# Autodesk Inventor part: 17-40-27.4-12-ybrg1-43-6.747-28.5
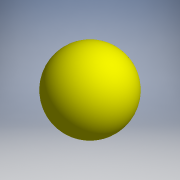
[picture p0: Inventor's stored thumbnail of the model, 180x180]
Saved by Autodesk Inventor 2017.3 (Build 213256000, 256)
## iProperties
Part Number: 17-40-27.4-12-ybrg1-43-6.747-28.5
Material: Generic
Catalog Web Link: www.cadenas.de
Description: Ball for Y units-Y-bearings
Vendor: SKF
Document SubType Name: Modeling
Designer: partserver
Manufacturer: SKF
Mass: 0.160817 g
Surface Area: 1.43012 cm^2
Volume: 0.160817 cm^3
Density: 1 g/cm^3
Appearance: PSOLRGB-255-255-0
Category: PARTsolutions
Company: SKF
Title: 17-40-27.4-12-ybrg1-43-6.747-28.5
Author: Cadenas PARTsolutions
Comments: Y-bearings
PSOL_IDENT_0: {$CADENAS_DATA\23d-libs\skf\bearings_units_and_housings\bearing_units\ball_bearing_units\y-unit_acce
PSOL_IDENT_1: ssories\ball.prj},218 {VTYP=3D},{NB=17-40-27.4-12-ybrg1-43-6.747-28.5},{LINA=17-40-27.4-12-ybrg1-43-
PSOL_IDENT_2: 6.747-28.5},{NN=Ball for Y units},{DATE=20.08.2020 13:45:09},{GEOMDATE=29.07.2020 16:06:32},{VERSION=
PSOL_IDENT_3: },{LINEID=1230},{WBVAR=},{WBNUMERIC=}  {NB=17-40-27.4-12-ybrg1-43-6.747-28.5},{LINA=17-40-27.4-12-yb
PSOL_IDENT_4: rg1-43-6.747-28.5},{KT=DUMMY},{DD=17.0000},{D=40},{B=27.400},{C=12.000},{PITCH=28.500},{DW=6.747},{F
PSOL_IDENT_5: O=IEC_BBY_006},{DESIGN=ybrg1},{X=0},{PN=43}
NB: 17-40-27.4-12-ybrg1-43-6.747-28.5
NN: Ball for Y units
NT: Y-bearings
NBSYN: $DD.-$D.-$B.-$C.-$DESIGN.-$PN.-$DW.-$PITCH.
LINA: 17-40-27.4-12-ybrg1-43-6.747-28.5
CATALOG: SKF
DD: 17
D: 40
B: 27.4
C: 12
PITCH: 28.5
DW: 6.747
FO: IEC_BBY_006
DESIGN: ybrg1
SUPPLIER: SKF
ARTICLENO: 17-40-27.4-12-ybrg1-43-6.747-28.5
BOMINFO: 17-40-27.4-12-ybrg1-43-6.747-28.5
CREATOR: CADENAS GmbH
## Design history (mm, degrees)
sketch "Sketch_1"
  geometry: L1 (3.374, 14.25)-(-3.374, 14.25); L2 (3.374, 14.25)-(-3.374, 14.25); A1 r 3.374 centre (0, 14.25) between (3.374, 14.25) and (-3.374, 14.25)
  constraints: 4 end point, 2 point on circle, 1 centre point
revolve "Revolution1" sketch "Sketch_1" stored, may be unused: angle "d0" = 360 deg
node "ball_XY"
node "ball_YZ"
node "ball_ZX"
node "ball_X"
node "ball_Y"
node "ball_Z"
node "ball_Center"
body "Solid1"
